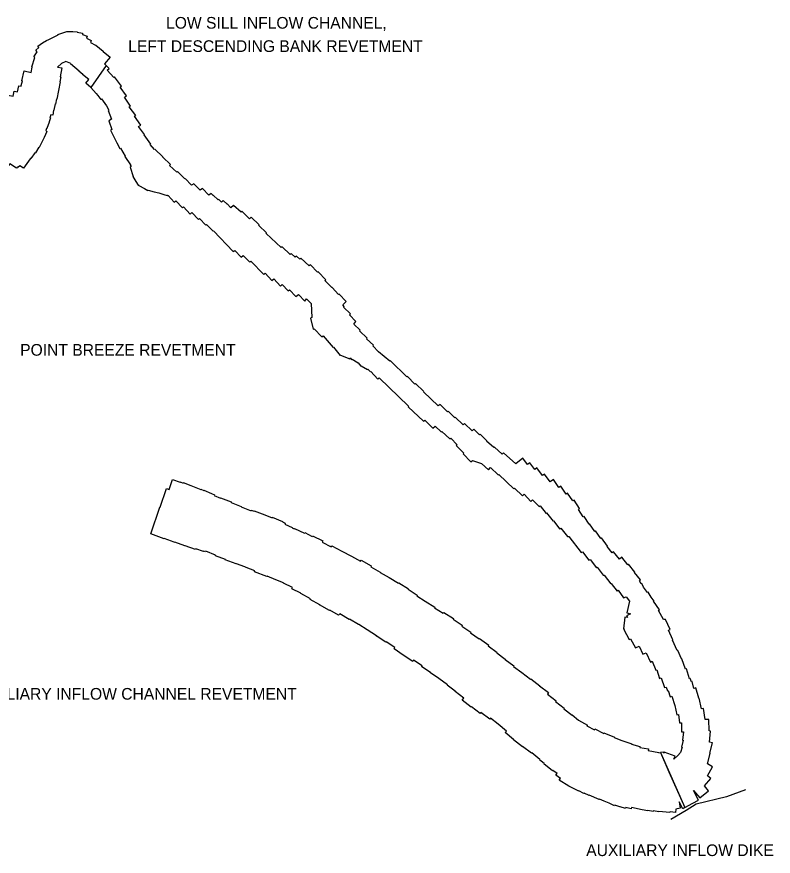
# Model space of a CAD drawing. Extents: x 2650582 to 3923188, y 277893 to 989177.
# Drawn here: x 3198891 to 3209243, y 927886 to 939373 of the extents above; entities that cross this region are included whole.
import ezdxf

# ---------------------------------------------------------------- set-up
doc = ezdxf.new("R2010")
doc.units = 0
doc.layers.add('Level 3', color=7, linetype='Continuous')

msp = doc.modelspace()

# ---------------------------------------------------------------- linework, layer by layer
at = {"layer": 'Level 3'}
for points in [[(3199087, 938611), (3199100, 938685), (3199096, 938686), (3199138, 938815), (3199125, 938825), (3199170, 938892), (3199151, 938914), (3199192, 938952), (3199180, 938970), (3199244, 939015), (3199242, 939018), (3199297, 939046), (3199331, 939064), (3199457, 939126), (3199455, 939130), (3199576, 939172), (3199576, 939171), (3199636, 939170), (3199655, 939173), (3199656, 939170), (3199719, 939169), (3199719, 939161), (3199792, 939147), (3199792, 939129), (3199855, 939109), (3199847, 939080), (3199910, 939049), (3199899, 939023), (3199969, 938983), (3199971, 938985), (3200075, 938903), (3200072, 938899), (3200168, 938820)], [(3200168, 938820), (3200093, 938727), (3200114, 938705), (3199903, 938404), (3199835, 938465), (3199877, 938513)], [(3199877, 938513), (3199792, 938582), (3199793, 938583), (3199740, 938627), (3199743, 938630), (3199627, 938730), (3199630, 938734), (3199564, 938761), (3199505, 938732), (3199450, 938684), (3199509, 938672)], [(3200154, 938665), (3200114, 938705), (3199903, 938404)], [(3199509, 938672), (3199485, 938551), (3199493, 938550), (3199480, 938483), (3199483, 938482), (3199440, 938247), (3199435, 938248), (3199422, 938179), (3199414, 938180), (3199397, 938093), (3199394, 938093), (3199383, 938027), (3199357, 938032), (3199344, 937992), (3199353, 937989), (3199333, 937933), (3199335, 937932), (3199304, 937842), (3199298, 937844), (3199288, 937815), (3199302, 937804), (3199264, 937723), (3199267, 937722), (3199197, 937585), (3199191, 937588), (3199149, 937513), (3199141, 937517), (3199083, 937432), (3199079, 937435), (3199074, 937429), (3199076, 937428), (3198983, 937301), (3198934, 937335)], [(3198951, 938424), (3198953, 938432), (3198952, 938432), (3198953, 938434), (3198951, 938434), (3198967, 938494), (3198961, 938495), (3198992, 938632), (3199087, 938611)], [(3201190, 937157), (3201089, 937255), (3201080, 937247), (3200981, 937338), (3200993, 937351), (3200889, 937452), (3200891, 937458), (3200779, 937563), (3200774, 937556), (3200717, 937624), (3200724, 937629), (3200634, 937758), (3200640, 937762), (3200558, 937871), (3200587, 937891), (3200503, 938011), (3200518, 938022), (3200431, 938139), (3200446, 938148), (3200365, 938271), (3200392, 938290), (3200305, 938410), (3200324, 938425), (3200229, 938549), (3200220, 938542), (3200128, 938643), (3200154, 938665)], [(3198566, 937938), (3198574, 937933), (3198591, 937963), (3198587, 937965), (3198644, 938083), (3198642, 938084), (3198663, 938138), (3198691, 938254), (3198707, 938251), (3198719, 938307), (3198842, 938285), (3198856, 938355), (3198900, 938347), (3198918, 938430), (3198951, 938424)], [(3199903, 938404), (3199979, 938322), (3200002, 938294), (3200043, 938243), (3200051, 938248), (3200118, 938154), (3200150, 938095), (3200141, 938090), (3200188, 937972), (3200149, 937950), (3200193, 937829), (3200173, 937819), (3200261, 937648), (3200302, 937571), (3200310, 937574), (3200374, 937466), (3200368, 937461), (3200446, 937349), (3200443, 937346), (3200458, 937325), (3200443, 937317), (3200483, 937187), (3200478, 937186), (3200522, 937117), (3200553, 937068), (3200565, 937069), (3200561, 937065), (3200638, 937022), (3200683, 936997), (3200689, 937002), (3200772, 936976), (3200835, 936962), (3200905, 936941), (3200950, 936926), (3200953, 936934), (3200958, 936926), (3200962, 936929), (3201046, 936834), (3201067, 936852), (3201159, 936759), (3201171, 936770), (3201263, 936672), (3201288, 936696), (3201376, 936601), (3201391, 936614), (3201479, 936522), (3201489, 936530), (3201577, 936438), (3201585, 936445)], [(3198934, 937335), (3198907, 937311), (3198901, 937318), (3198889, 937299), (3198797, 937360), (3198757, 937305), (3198751, 937309), (3198714, 937257), (3198670, 937288), (3198603, 937199), (3198525, 937257)], [(3201578, 936928), (3201553, 936956), (3201521, 936930), (3201431, 937024), (3201399, 936998), (3201312, 937088), (3201284, 937067), (3201195, 937162), (3201190, 937157)], [(3201973, 936711), (3201960, 936697), (3201858, 936792), (3201821, 936760), (3201771, 936812), (3201769, 936810), (3201717, 936859), (3201693, 936837), (3201656, 936874), (3201646, 936867), (3201580, 936930), (3201578, 936928)], [(3202702, 936082), (3202645, 936134), (3202631, 936121), (3202521, 936227), (3202507, 936214), (3202303, 936409), (3202309, 936415), (3202205, 936518), (3202209, 936524), (3202098, 936631), (3202075, 936608), (3201973, 936711)], [(3201585, 936445), (3201852, 936159), (3201874, 936175), (3201960, 936082), (3201989, 936105), (3202080, 936015), (3202093, 936027), (3202270, 935845), (3202291, 935864), (3202380, 935765), (3202407, 935788), (3202500, 935687), (3202525, 935709), (3202605, 935623), (3202622, 935638), (3202711, 935545), (3202746, 935574), (3202831, 935483), (3202858, 935511)], [(3203203, 935667), (3203108, 935764), (3203120, 935775), (3203017, 935884), (3203008, 935878), (3202910, 935979), (3202893, 935963), (3202780, 936068), (3202764, 936054), (3202721, 936099), (3202702, 936082)], [(3203352, 935433), (3203397, 935475), (3203302, 935577), (3203294, 935571), (3203205, 935669), (3203203, 935667)], [(3202858, 935511), (3202918, 935448)], [(3202918, 935448), (3202928, 935256), (3202909, 935249), (3202947, 935099), (3202960, 935101), (3203068, 934993), (3203083, 935007), (3203219, 934845), (3203225, 934850), (3203317, 934739), (3203323, 934742), (3203447, 934692), (3203454, 934705), (3203473, 934682), (3203482, 934687), (3203561, 934638), (3203600, 934593), (3203606, 934598), (3203691, 934545), (3203695, 934552), (3203730, 934514), (3203737, 934518), (3203831, 934414), (3203852, 934433)], [(3204231, 934445), (3204007, 934666), (3203997, 934660), (3203843, 934789), (3203762, 934870), (3203771, 934879), (3203679, 934968), (3203686, 934977), (3203583, 935077), (3203589, 935083), (3203505, 935167), (3203531, 935201), (3203444, 935294), (3203456, 935308), (3203364, 935400), (3203373, 935410), (3203352, 935433)], [(3203852, 934433), (3204254, 934043), (3204249, 934037), (3204456, 933837), (3204475, 933852), (3204584, 933745), (3204615, 933769), (3204701, 933694), (3204709, 933697), (3204816, 933597), (3204833, 933606), (3204919, 933517), (3204906, 933505), (3205011, 933401), (3205002, 933392), (3205106, 933282), (3205129, 933299), (3205249, 933258), (3205347, 933174), (3205375, 933203), (3205480, 933103), (3205487, 933110), (3205694, 932913), (3205701, 932922), (3205813, 932817), (3205837, 932838), (3205927, 932741), (3205950, 932765), (3206042, 932670), (3206056, 932681), (3206134, 932577), (3206142, 932585), (3206230, 932469), (3206237, 932474), (3206324, 932363)], [(3205818, 933332), (3205720, 933257), (3205554, 933406), (3205536, 933388), (3205429, 933485), (3205419, 933479), (3205321, 933566), (3205326, 933572), (3205231, 933661), (3205224, 933652), (3205147, 933732), (3205122, 933708), (3205018, 933808), (3204998, 933789), (3204889, 933892), (3204884, 933886), (3204794, 933974), (3204785, 933966), (3204684, 934066), (3204659, 934049), (3204455, 934241), (3204460, 934245), (3204348, 934354), (3204340, 934347), (3204236, 934449), (3204231, 934445)], [(3207413, 931654), (3207428, 931666), (3207347, 931767), (3207351, 931772), (3207264, 931881), (3207253, 931872), (3207172, 931976), (3207139, 931950), (3207058, 932052), (3207041, 932039), (3206973, 932125), (3206974, 932127), (3206892, 932241), (3206883, 932234), (3206809, 932338), (3206802, 932331), (3206731, 932435), (3206723, 932429), (3206654, 932536), (3206643, 932529), (3206577, 932632), (3206593, 932642), (3206517, 932760), (3206499, 932748), (3206429, 932856), (3206408, 932842), (3206337, 932949), (3206309, 932931), (3206236, 933040), (3206190, 933010), (3206115, 933116), (3206088, 933097), (3206008, 933200), (3205979, 933179), (3205911, 933271), (3205882, 933247), (3205818, 933332)], [(3200850, 932664), (3200851, 932663), (3200938, 932916), (3200976, 932903), (3201024, 933043)], [(3201024, 933043), (3201128, 933005), (3201129, 933007), (3201167, 932993), (3201170, 932999), (3201271, 932959), (3201271, 932960), (3201409, 932903), (3201411, 932908), (3201452, 932891), (3201453, 932893), (3201556, 932851), (3201556, 932849), (3201597, 932833), (3201594, 932824), (3201680, 932787), (3201681, 932790), (3201826, 932734), (3201823, 932725), (3201963, 932670), (3201962, 932666), (3202097, 932613), (3202100, 932621), (3202139, 932607), (3202141, 932614), (3202286, 932558), (3202285, 932556), (3202384, 932518), (3202386, 932524), (3202529, 932464), (3202527, 932461), (3202565, 932444), (3202560, 932432), (3202659, 932383), (3202658, 932381), (3202689, 932366), (3202692, 932371), (3202829, 932307)], [(3202541, 931626), (3202437, 931670), (3202316, 931717), (3202315, 931714), (3202146, 931779), (3202150, 931789), (3202031, 931836), (3202032, 931839), (3202013, 931846), (3202012, 931844), (3201896, 931889), (3201895, 931885), (3201745, 931943), (3201746, 931946), (3201609, 931998), (3201612, 932006), (3201476, 932059), (3201473, 932053), (3201449, 932062), (3201446, 932055), (3201341, 932092), (3201339, 932085), (3201194, 932135), (3201193, 932134), (3201053, 932183), (3201052, 932181), (3201008, 932195), (3201009, 932196), (3200906, 932232), (3200906, 932230), (3200762, 932283), (3200762, 932284), (3200724, 932298), (3200850, 932664)], [(3206324, 932363), (3206337, 932373), (3206427, 932260), (3206447, 932262), (3206614, 932041), (3206633, 932050), (3206718, 931936), (3206737, 931945), (3206823, 931832), (3206832, 931840), (3206918, 931734), (3206931, 931733), (3207019, 931613), (3207027, 931619), (3207109, 931514), (3207120, 931526), (3207196, 931420), (3207229, 931436), (3207277, 931376)], [(3202829, 932307), (3202832, 932314), (3202934, 932263), (3202938, 932272), (3203078, 932201), (3203070, 932184), (3203194, 932119), (3203201, 932133), (3203340, 932062), (3203339, 932061), (3203474, 931991), (3203473, 931990), (3203597, 931922), (3203605, 931936), (3203742, 931859), (3203735, 931846), (3203865, 931772), (3203863, 931770), (3203986, 931698), (3203987, 931700), (3204115, 931623), (3204118, 931629), (3204250, 931544), (3204248, 931540), (3204370, 931460), (3204364, 931450), (3204479, 931375), (3204480, 931377), (3204612, 931292), (3204608, 931286), (3204728, 931210), (3204737, 931223), (3204867, 931137), (3204863, 931131), (3204988, 931047), (3204980, 931034), (3205104, 930950), (3205099, 930941), (3205219, 930861), (3205223, 930866), (3205351, 930776), (3205341, 930763), (3205464, 930674), (3205460, 930668)], [(3204180, 930637), (3204181, 930639), (3204055, 930722), (3204067, 930741), (3203945, 930820), (3203941, 930814), (3203810, 930900), (3203812, 930904), (3203686, 930986), (3203687, 930986), (3203570, 931059), (3203568, 931056), (3203444, 931130), (3203441, 931126), (3203310, 931205), (3203296, 931183), (3203177, 931255), (3203172, 931247), (3203036, 931325), (3203038, 931328), (3202906, 931401), (3202909, 931406), (3202778, 931480), (3202780, 931484), (3202657, 931547), (3202664, 931563), (3202539, 931623), (3202541, 931626)], [(3208125, 930272), (3208108, 930316), (3208098, 930315), (3208057, 930449), (3208042, 930447), (3207994, 930586), (3207986, 930585), (3207939, 930702), (3207930, 930699), (3207865, 930842), (3207870, 930846), (3207810, 930979), (3207831, 930989), (3207768, 931124), (3207743, 931123), (3207675, 931247), (3207685, 931256), (3207684, 931256), (3207685, 931257), (3207604, 931374), (3207613, 931377), (3207571, 931433), (3207533, 931501), (3207524, 931496), (3207469, 931569), (3207443, 931617), (3207438, 931614), (3207413, 931654)], [(3207277, 931376), (3207241, 931217), (3207288, 931203), (3207236, 931177), (3207250, 931151), (3207214, 931155), (3207193, 930998), (3207209, 930996), (3207198, 930987), (3207272, 930851), (3207291, 930861), (3207360, 930738), (3207407, 930759), (3207457, 930650), (3207503, 930671), (3207562, 930543), (3207587, 930553), (3207635, 930431), (3207649, 930436), (3207688, 930320), (3207711, 930327), (3207755, 930195), (3207777, 930199), (3207795, 930150)], [(3205460, 930668), (3205576, 930583), (3205573, 930579), (3205695, 930492), (3205689, 930482), (3205801, 930399), (3205803, 930401), (3205923, 930311), (3205924, 930313), (3206049, 930218), (3206047, 930216), (3206167, 930125), (3206152, 930105), (3206271, 930012), (3206265, 930005), (3206383, 929911), (3206379, 929905), (3206490, 929815), (3206493, 929819), (3206579, 929749), (3206700, 929679), (3206694, 929668), (3206796, 929616), (3206801, 929627), (3206923, 929567), (3206926, 929575), (3207070, 929513), (3207068, 929510), (3207170, 929468), (3207307, 929423), (3207305, 929418), (3207420, 929389), (3207416, 929375), (3207535, 929354), (3207531, 929331), (3207678, 929305), (3207677, 929302), (3207699, 929304)], [(3205007, 930049), (3204891, 930141), (3204892, 930144), (3204782, 930225), (3204786, 930230), (3204666, 930318), (3204666, 930320), (3204554, 930396), (3204555, 930398), (3204433, 930477), (3204441, 930490), (3204322, 930569), (3204310, 930551), (3204180, 930637)], [(3208376, 929295), (3208411, 929437), (3208371, 929446), (3208386, 929598), (3208367, 929601), (3208362, 929757), (3208310, 929755), (3208290, 929907), (3208264, 929904), (3208232, 930050), (3208226, 930048), (3208184, 930189), (3208159, 930182), (3208133, 930275), (3208125, 930272)], [(3207795, 930150), (3207806, 930153), (3207833, 930069), (3207857, 930076), (3207896, 929949), (3207911, 929885), (3207926, 929820), (3207947, 929825), (3207960, 929710), (3207986, 929712), (3207990, 929590), (3208015, 929589), (3208003, 929476), (3208013, 929475), (3207990, 929380), (3207995, 929379)], [(3205996, 929257), (3205940, 929301), (3205937, 929295), (3205814, 929386), (3205812, 929383), (3205689, 929480), (3205690, 929482), (3205577, 929578), (3205592, 929596), (3205477, 929694), (3205478, 929695), (3205373, 929776), (3205363, 929762), (3205243, 929852), (3205232, 929838), (3205113, 929930), (3205110, 929926), (3204987, 930022), (3205007, 930049)], [(3207995, 929379), (3207974, 929303), (3207940, 929262), (3207885, 929214), (3207900, 929257), (3207753, 929309), (3207748, 929297), (3207747, 929309), (3207699, 929304), (3208033, 928551)], [(3207699, 929304), (3207817, 929039), (3208033, 928551), (3208006, 928536)], [(3208033, 928551), (3208144, 928610), (3208143, 928612), (3208221, 928653), (3208154, 928784), (3208241, 928683), (3208358, 928782), (3208303, 928847), (3208389, 928948), (3208344, 928986), (3208411, 929110), (3208342, 929148), (3208381, 929293), (3208376, 929295)], [(3208006, 928536), (3207956, 928631), (3207972, 928542), (3207910, 928531), (3207905, 928486), (3207831, 928493), (3207830, 928482), (3207677, 928497), (3207677, 928494), (3207603, 928505), (3207602, 928498), (3207527, 928512), (3207526, 928508), (3207451, 928522), (3207450, 928520), (3207302, 928551), (3207298, 928535), (3207224, 928552), (3207221, 928541), (3207147, 928564), (3207146, 928561), (3207076, 928583), (3207072, 928575), (3206998, 928610), (3206928, 928638), (3206928, 928640), (3206865, 928667), (3206862, 928660), (3206726, 928721), (3206723, 928716), (3206655, 928750), (3206652, 928745), (3206584, 928779), (3206581, 928774), (3206447, 928846), (3206445, 928844), (3206315, 928928), (3206331, 928951), (3206270, 928996), (3206285, 929016), (3206228, 929061), (3206223, 929055), (3206102, 929150), (3206107, 929156), (3206045, 929204), (3206049, 929210), (3205993, 929254), (3205996, 929257)], [(3208865, 928795), (3208606, 928697), (3208190, 928597), (3208050, 928513), (3207841, 928388)]]:
    msp.add_lwpolyline(points, dxfattribs=at)

# ---------------------------------------------------------------- texts
for s, p in [('LOW SILL INFLOW CHANNEL,', (3200934, 939210)), ('LEFT DESCENDING BANK REVETMENT', (3200416, 938891)), ('POINT BREEZE REVETMENT', (3198937, 934735)), ('AUXILIARY INFLOW CHANNEL REVETMENT', (3198252, 930028)), ('AUXILIARY INFLOW DIKE', (3206684, 927888))]:
    msp.add_text(s, height=160, dxfattribs=at).set_placement(p)

doc.saveas('drawing.dxf')
